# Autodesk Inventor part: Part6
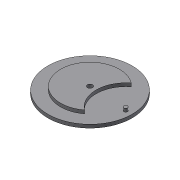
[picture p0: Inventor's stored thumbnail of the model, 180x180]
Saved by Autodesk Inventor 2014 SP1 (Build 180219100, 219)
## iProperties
Created: 2014-01
Part Number: Part6
Material: 一般
Document SubType Name: Modeling
Designer: Hashimoto
Density: 1 g/cm^3
Appearance: 既定
Mass: 683.104 g
Surface Area: 1158.58 cm^2
Volume: 683.104 cm^3
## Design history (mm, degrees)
sketch "スケッチ3"
  geometry: C1 r 7.938 at (279.541, -0.279); C2 r 127 at (279.541, -0.279); C3 r 5.556 at (387.491, -0.387); C4 r 5.556 at (387.491, -0.387); A1 r 88.9 centre (387.491, -0.387) between (333.587, 70.306) and (333.446, -70.973); A2 r 88.9 centre (279.541, -0.279) between (333.587, 70.306) and (333.446, -70.973); A3 r 88.9 centre (279.541, -0.279) between (333.587, 70.306) and (333.446, -70.973); A4 r 88.9 centre (387.491, -0.387) between (333.587, 70.306) and (333.446, -70.973); 1 further point
  constraints: 8 centre point, 8 point on circle
extrude "押し出し3" new body sketch "スケッチ3" distance "d6" = 10; taper "d7" = 0 deg
sketch "スケッチ4"
  geometry: C1 r 7.937 at (0, 0) reference; A1 r 88.9 centre (0, 0) between (54.046, 70.585) and (53.904, -70.693); A2 r 88.9 centre (107.95, -0.108) between (54.046, 70.585) and (53.904, -70.693); 1 further point
  constraints: 4 point on circle, 2 centre point
extrude "押し出し4" join sketch "スケッチ4" distance "d8" = 10; taper "d9" = 0 deg
sketch "スケッチ5"
  geometry: C1 r 5.556 at (107.95, -0.108); 1 further point
  constraints: 1 centre point
extrude "押し出し5" join sketch "スケッチ5" distance "d10" = 10; taper "d11" = 0 deg
node "ソリッド3"
